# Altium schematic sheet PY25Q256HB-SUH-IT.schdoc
size 127 x 101 mm
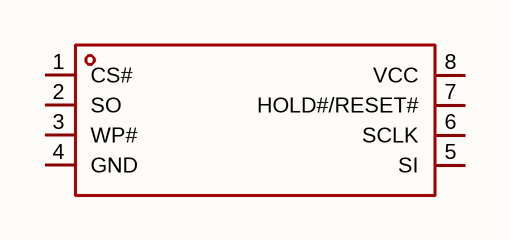
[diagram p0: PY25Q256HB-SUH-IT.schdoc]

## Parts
U?  py25q256hb-suh-it  [SOP-8_L5.3-W5.3-P1.27-LS8.0-BL]  (value not drawn)

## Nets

Not connected (* = marked no-connect by the designer): U? 1(CS#) 2(SO) 3(WP#) 4(GND) 5(SI) 6(SCLK) 7(HOLD#/RESET#) 8(VCC)

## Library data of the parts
U? = py25q256hb-suh-it: 接口类型:SPI;存储容量:256Mbit;时钟频率(fc):133MHz;; Manufacturer: PUYA(普冉); AddInBom: yes; ModelId: e456afcfff5840a795bdd4917416584f; ModelName: SOP-8_L5.2-W5.3-H2.1-LS7.9-P1.27; ModelTransform: 311.024,204.724,0,90,0,0,0,0.0005,0; Interface: SPI; Clock Frequency: 133MHz; Voltage - Supply: 2.7V~3.6V; Standby Supply Current: 20uA; Program / Erase Cycles: 100000次; Write Cycle Time (tWC): 2ms; Page Programming Time (Tpp): 250us; Block Erase Time(tBE): 150ms; Data Retention - TDR (Year): 20年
